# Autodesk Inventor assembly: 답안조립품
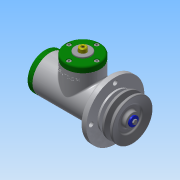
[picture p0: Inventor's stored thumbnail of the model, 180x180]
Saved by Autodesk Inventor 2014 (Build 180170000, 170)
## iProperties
Created: 2016-08
Part Number: 답안조립품
Document SubType Name: Assembly
Designer: 703-04
Author: 703-04
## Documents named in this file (25)
- C:\Users\703-04\Desktop\460808V1013\답안조립품.iam
- C:\Users\703-04\Desktop\460808V1013\본체.ipt
- C:\Users\703-04\Desktop\460808V1013\사이드 커버.ipt
- 사이드 커버.ipt
- C:\Users\703-04\Desktop\460808V1013\탑 커버.ipt
- 탑 커버.ipt
- C:\Users\703-04\Desktop\460808V1013\탑 부시.ipt
- C:\Users\703-04\Desktop\460808V1013\슬라이더.ipt
- C:\Users\703-04\Desktop\460808V1013\볼트 M4 x 12.ipt
- C:\Users\703-04\Desktop\460808V1013\멈춤링 35x1.6.ipt
- C:\Users\703-04\Desktop\460808V1013\베어링 15 x 35 x 11.ipt
- C:\Users\703-04\Desktop\460808V1013\멈춤링 15 x 1.ipt
- C:\Users\703-04\Desktop\460808V1013\편심축.ipt
- C:\Users\703-04\Desktop\460808V1013\부시1.ipt
- C:\Users\703-04\Desktop\460808V1013\부시2.ipt
- C:\Users\703-04\Desktop\460808V1013\와셔 10x21.ipt
- C:\Users\703-04\Desktop\460808V1013\와셔 4x16.ipt
- C:\Users\703-04\Desktop\460808V1013\너트 M10.ipt
- C:\Users\703-04\Desktop\460808V1013\오일 실 15 25 7.ipt
- C:\Users\703-04\Desktop\460808V1013\키 4 x 4 x 18.ipt
- C:\Users\703-04\Desktop\460808V1013\볼트 M4 x 10.ipt
- C:\Users\703-04\Desktop\460808V1013\V-벨트풀리.ipt
- C:\Users\703-04\Desktop\460808V1013\분할핀 1.6 x 12.ipt
- C:\Users\703-04\Desktop\460808V1013\링크.ipt
- C:\Users\703-04\Desktop\460808V1013\클래스터 핀 6 x 24.ipt
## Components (6 placed, 3 different names)
1. ISO 4017 M4 x 10:1
2. V-벨트풀리:1 — 각도:2
3. ISO 4762 M4 x 12:1
4. ISO 4762 M4 x 12:2
5. ISO 4762 M4 x 12:3
6. ISO 4762 M4 x 12:4
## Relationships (1: Angle 1)
- 각도:2 [Angle]: V-벨트풀리:1
